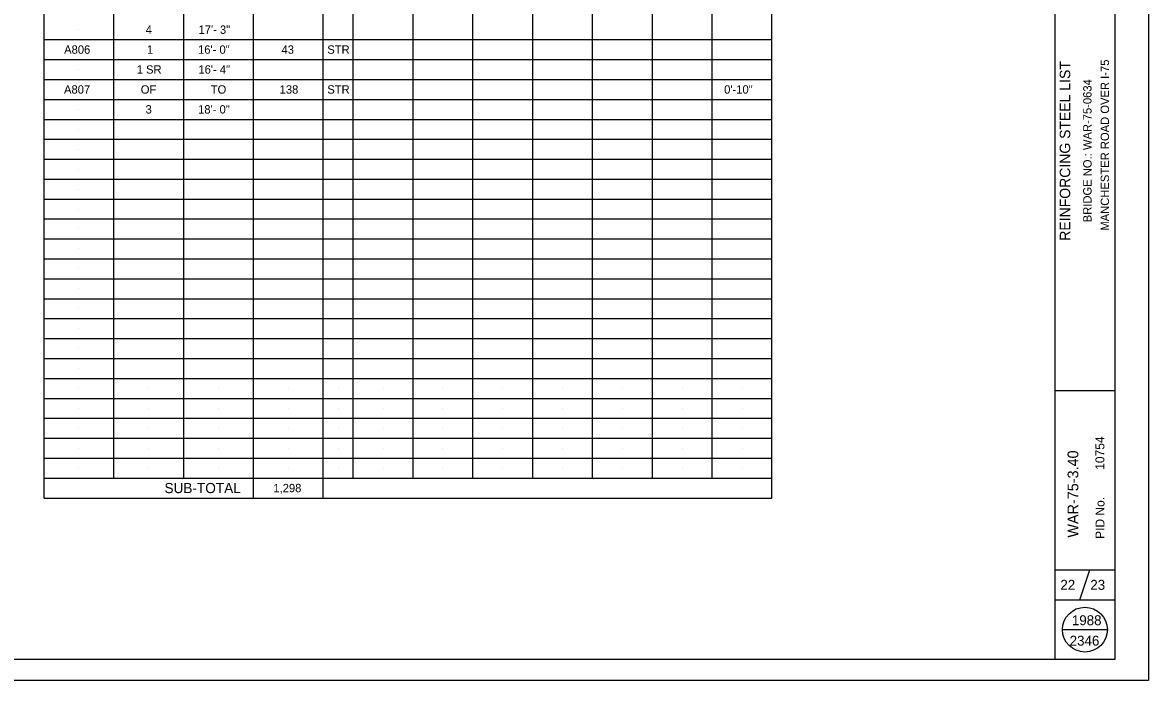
# Model space of a CAD drawing. Extents: x -9.2 to 26.7, y -24.6 to -2.6.
# Drawn here: x 7.28 to 26.1, y -24.46 to -13.46 of the extents above; entities that cross this region are included whole.
import ezdxf

# ---------------------------------------------------------------- set-up
doc = ezdxf.new("R2010")
doc.units = 0
for name, color, linetype in [('BR_P_Gen_Text', 7, 'Continuous'), ('SC_Scratch1', 7, 'Continuous'), ('SH_Border', 7, 'Continuous'), ('SH_Cut_Line', 7, 'Continuous'), ('SH_Data', 7, 'Continuous'), ('TX_P_1', 7, 'Continuous')]:
    doc.layers.add(name, color=color, linetype=linetype)

msp = doc.modelspace()

# ---------------------------------------------------------------- linework, layer by layer
at = {"layer": 'BR_P_Gen_Text'}
for p, q in [((7.637, -21.411), (7.637, -3.594)), ((19.803, -21.411), (19.803, -3.594)), ((8.804, -21.078), (8.804, -5.411)), ((9.971, -21.078), (9.971, -5.411)), ((11.138, -21.411), (11.137, -5.411)), ((12.304, -21.411), (12.304, -5.411)), ((12.804, -21.078), (12.804, -5.411)), ((13.804, -21.078), (13.804, -5.411)), ((14.804, -21.078), (14.804, -5.411)), ((15.804, -21.078), (15.804, -5.411)), ((16.804, -21.078), (16.804, -5.411)), ((17.804, -21.078), (17.804, -5.411)), ((18.804, -21.078), (18.804, -5.411)), ((7.637, -13.744), (19.803, -13.744)), ((7.637, -14.078), (19.803, -14.078)), ((7.637, -14.411), (19.803, -14.411)), ((7.637, -14.744), (19.803, -14.745)), ((7.637, -15.078), (19.803, -15.078)), ((7.637, -15.411), (19.803, -15.411)), ((7.637, -15.744), (19.803, -15.744)), ((7.637, -16.078), (19.803, -16.078)), ((7.637, -16.411), (19.803, -16.411)), ((7.637, -16.744), (19.804, -16.744)), ((7.637, -17.078), (19.804, -17.078)), ((7.637, -17.411), (19.804, -17.411)), ((7.637, -17.744), (19.804, -17.744)), ((7.637, -18.078), (19.803, -18.078)), ((7.637, -18.411), (19.803, -18.411)), ((7.637, -18.744), (19.804, -18.744)), ((7.637, -19.078), (19.804, -19.078)), ((7.637, -19.411), (19.804, -19.411)), ((7.637, -19.744), (19.803, -19.744)), ((7.637, -20.078), (19.803, -20.078)), ((7.637, -20.411), (19.803, -20.411)), ((7.637, -20.744), (19.803, -20.744)), ((7.637, -21.078), (19.803, -21.078)), ((7.637, -21.411), (19.803, -21.411)), ((7.637, -21.411), (19.803, -21.411))]:
    msp.add_line(p, q, dxfattribs=at)
at = {"layer": 'SC_Scratch1'}
for p, q in [((8.221, -13.578), (8.221, -13.578)), ((8.221, -13.911), (8.221, -13.911)), ((8.221, -14.244), (8.221, -14.244)), ((8.221, -14.578), (8.221, -14.578)), ((8.221, -14.911), (8.221, -14.911)), ((8.221, -15.244), (8.221, -15.244)), ((8.221, -15.578), (8.221, -15.578)), ((8.221, -15.911), (8.221, -15.911)), ((8.221, -16.244), (8.221, -16.244)), ((8.221, -16.578), (8.221, -16.578)), ((8.221, -16.911), (8.221, -16.911)), ((8.221, -17.244), (8.221, -17.244)), ((8.221, -17.578), (8.221, -17.578)), ((8.221, -17.911), (8.221, -17.911)), ((8.221, -18.244), (8.221, -18.244)), ((8.221, -18.578), (8.221, -18.578)), ((8.221, -18.911), (8.221, -18.911)), ((8.221, -19.244), (8.221, -19.244)), ((8.221, -19.578), (8.221, -19.578)), ((8.221, -19.578), (8.221, -19.578)), ((9.388, -19.578), (9.388, -19.578)), ((10.554, -19.578), (10.554, -19.578)), ((11.721, -19.578), (11.721, -19.578)), ((12.554, -19.578), (12.554, -19.578)), ((13.304, -19.578), (13.304, -19.578)), ((14.304, -19.578), (14.304, -19.578)), ((15.304, -19.578), (15.304, -19.578)), ((16.304, -19.578), (16.304, -19.578)), ((17.304, -19.578), (17.304, -19.578)), ((18.304, -19.578), (18.304, -19.578)), ((19.304, -19.578), (19.304, -19.578)), ((8.221, -19.911), (8.221, -19.911)), ((9.387, -19.911), (9.387, -19.911)), ((10.554, -19.911), (10.554, -19.911)), ((11.721, -19.911), (11.721, -19.911)), ((12.554, -19.911), (12.554, -19.911)), ((13.304, -19.911), (13.304, -19.911)), ((14.304, -19.911), (14.304, -19.911)), ((15.304, -19.911), (15.304, -19.911)), ((16.304, -19.911), (16.304, -19.911)), ((17.304, -19.911), (17.304, -19.911)), ((18.304, -19.911), (18.304, -19.911)), ((19.304, -19.911), (19.304, -19.911)), ((8.221, -20.244), (8.221, -20.244)), ((9.387, -20.244), (9.387, -20.244)), ((10.554, -20.244), (10.554, -20.244)), ((11.721, -20.244), (11.721, -20.244)), ((12.554, -20.244), (12.554, -20.244)), ((13.304, -20.244), (13.304, -20.244)), ((14.304, -20.244), (14.304, -20.244)), ((15.304, -20.244), (15.304, -20.244)), ((16.304, -20.244), (16.304, -20.244)), ((17.304, -20.244), (17.304, -20.244)), ((18.304, -20.244), (18.304, -20.244)), ((19.303, -20.244), (19.303, -20.244)), ((8.221, -20.578), (8.221, -20.578)), ((9.387, -20.578), (9.387, -20.578)), ((10.554, -20.578), (10.554, -20.578)), ((11.721, -20.578), (11.721, -20.578)), ((12.554, -20.578), (12.554, -20.578)), ((13.304, -20.578), (13.304, -20.578)), ((14.304, -20.578), (14.304, -20.578)), ((15.304, -20.578), (15.304, -20.578)), ((16.304, -20.578), (16.304, -20.578)), ((17.303, -20.578), (17.303, -20.578)), ((18.303, -20.578), (18.303, -20.578)), ((19.303, -20.578), (19.303, -20.578)), ((8.221, -20.911), (8.221, -20.911)), ((9.387, -20.911), (9.387, -20.911)), ((10.554, -20.911), (10.554, -20.911)), ((11.721, -20.911), (11.721, -20.911)), ((12.554, -20.911), (12.554, -20.911)), ((13.304, -20.911), (13.304, -20.911)), ((14.304, -20.911), (14.304, -20.911)), ((15.304, -20.911), (15.304, -20.911)), ((16.304, -20.911), (16.304, -20.911)), ((17.304, -20.911), (17.304, -20.911)), ((18.304, -20.911), (18.304, -20.911)), ((19.304, -20.911), (19.304, -20.911)), ((11.72, -21.244), (11.72, -21.244))]:
    msp.add_line(p, q, dxfattribs=at)
at = {"layer": 'SH_Border'}
for p, q in [((24.534, -24.112), (24.534, -3.112)), ((24.534, -19.612), (25.534, -19.612)), ((24.534, -22.612), (25.534, -22.612)), ((24.95, -23.112), (25.117, -22.612)), ((24.534, -23.112), (25.534, -23.112))]:
    msp.add_line(p, q, dxfattribs=at)
msp.add_lwpolyline([(-5.966, -3.112), (25.534, -3.112), (25.534, -24.112), (-5.966, -24.112)], close=True, dxfattribs=at)
at = {"layer": 'SH_Cut_Line'}
msp.add_lwpolyline([(26.096, -24.462), (-7.904, -24.462), (-7.904, -2.812), (26.096, -2.812)], close=True, dxfattribs=at)
at = {"layer": 'SH_Data'}
msp.add_line((24.659, -23.612), (25.409, -23.612), dxfattribs=at)
msp.add_circle((25.034, -23.612), 0.375, dxfattribs=at)

# ---------------------------------------------------------------- texts
at = {"layer": 'BR_P_Gen_Text'}
for s, p in [('4', (9.336, -13.648)), (' 17\'- 3"', (10.167, -13.648)), ('A806', (7.973, -13.981)), ('1', (9.358, -13.981)), (' 16\'- 0"', (10.159, -13.981)), ('43', (11.606, -13.981)), ('STR', (12.371, -13.981)), ('1 SR', (9.186, -14.314)), (' 16\'- 4"', (10.165, -14.314)), ('A807', (7.971, -14.648)), ('OF', (9.254, -14.648)), ('TO', (10.423, -14.648)), ('138', (11.575, -14.648)), ('STR', (12.371, -14.648)), ('0\'-10"', (19.004, -14.648)), ('3', (9.334, -14.981)), (' 18\'- 0"', (10.16, -14.981)), ('1,298', (11.47, -21.314))]:
    msp.add_text(s, height=0.14, dxfattribs=at).set_placement(p)
at = {"layer": 'SH_Data'}
for s, height, p in [('REINFORCING STEEL LIST', 0.175, (24.788, -17.108)), ('MANCHESTER ROAD OVER I-75', 0.14, (25.437, -16.939)), ('BRIDGE NO.: WAR-75-0634', 0.14, (25.145, -16.799)), (' 10754', 0.15, (25.359, -20.994)), ('WAR-75-3.40', 0.18, (24.924, -22.073)), ('PID No.', 0.15, (25.361, -22.094))]:
    msp.add_text(s, height=height, rotation=90, dxfattribs=at).set_placement(p)
for s, p in [(' 22', (24.562, -22.946)), (' 23', (25.062, -22.946)), ('1988', (24.816, -23.538)), ('2346', (24.779, -23.88))]:
    msp.add_text(s, height=0.1666, dxfattribs=at).set_placement(p)
at = {"layer": 'TX_P_1'}
msp.add_text('SUB-TOTAL', height=0.17, dxfattribs=at).set_placement((9.65, -21.329))

doc.saveas('drawing.dxf')
